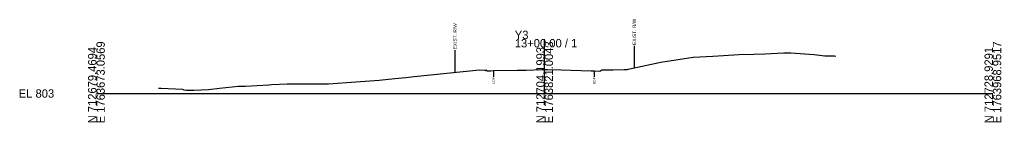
# Model space of a CAD drawing. Extents: x -26 to 2903, y -10 to 5022.
# Drawn here: x -25.7 to 302.8, y 2990.3 to 3024.8 of the extents above; entities that cross this region are included whole.
import ezdxf

# ---------------------------------------------------------------- set-up
doc = ezdxf.new("R2010")
doc.units = 0
for name, color, linetype in [('Default', 7, 'Continuous'), ('Exist Cross Section Cell', 7, 'Continuous'), ('Exist XS Ground Line', 7, 'Continuous'), ('Old_Level_10', 7, 'Continuous')]:
    doc.layers.add(name, color=color, linetype=linetype)

msp = doc.modelspace()

# ---------------------------------------------------------------- linework, layer by layer
at = {"layer": 'Exist Cross Section Cell'}
for p, q in [((150, 3000), (150, 3018.27)), ((0, 3000), (150, 3000)), ((150, 3000), (300, 3000))]:
    msp.add_line(p, q, dxfattribs=at)
at = {"layer": 'Exist XS Ground Line'}
msp.add_lwpolyline([(20.83, 3001.83), (21.66, 3001.81), (28.78, 3001.48), (29.25, 3001.28), (30.14, 3001.15), (32.55, 3001.09), (37.46, 3001.31), (41.24, 3001.83), (47.59, 3002.5), (49.93, 3002.41), (57.73, 3002.95), (58.61, 3002.97), (63.87, 3003.21), (67.3, 3003.22), (67.87, 3003.22), (68.71, 3003.25), (77.64, 3003.29), (83.66, 3003.69), (94.58, 3004.44), (99.87, 3005.07), (103.6, 3005.37), (106.37, 3005.72), (128.17, 3007.9), (129.89, 3007.87), (130.08, 3007.68), (130.2, 3007.67), (130.34, 3007.93), (130.88, 3007.56), (132, 3007.64), (132.83, 3007.69), (140.85, 3007.81), (143.79, 3007.85), (149.05, 3008), (150, 3008.03), (150.04, 3008.03), (150.91, 3008.02), (155.55, 3007.95), (165.56, 3007.66), (166.56, 3007.63), (166.72, 3007.63), (168.45, 3007.5), (168.51, 3007.54), (169.11, 3007.95), (171.73, 3007.94), (171.92, 3007.94), (172.86, 3007.97), (176.65, 3008.07), (177.59, 3008.1), (177.78, 3008.1), (177.91, 3008.14), (188.91, 3010.48), (189.54, 3010.63), (197.6, 3011.82), (199.68, 3012.15), (206.29, 3012.51), (209.81, 3012.79), (214.97, 3013.14), (219.95, 3013.17), (223.66, 3013.31), (230.09, 3013.63), (232.35, 3013.63), (240.23, 3013.14), (243.78, 3012.64), (246.96, 3012.67), (247.43, 3012.54)], dxfattribs=at)
at = {"layer": 'Old_Level_10'}
for p, q in [((180, 3015.98), (180, 3008.58)), ((120, 3014.49), (120, 3007.08)), ((132.83, 3007.69), (132.83, 3005.64)), ((166.56, 3007.63), (166.56, 3005.58))]:
    msp.add_line(p, q, dxfattribs=at)

# ---------------------------------------------------------------- texts
at = {"layer": 'Default'}
msp.add_text('-', height=0.0001, dxfattribs=at).set_placement((0, 3000))
at = {"layer": 'Exist Cross Section Cell'}
for s, p in [('Y3', (140, 3018.27)), ('13+00.00 / 1', (140, 3015.47)), ('EL 803', (-26, 2998.6))]:
    msp.add_text(s, height=2.8, dxfattribs=at).set_placement(p)
for s, p in [('E 1763673.0569', (2.8, 2990)), ('E 1763821.0043', (152.8, 2990)), ('E 1763968.9517', (302.8, 2990)), ('N 712679.4694', (0, 2990)), ('N 712704.1993', (150, 2990)), ('N 712728.9291', (300, 2990))]:
    msp.add_text(s, height=2.8, rotation=90, dxfattribs=at).set_placement(p)
at = {"layer": 'Old_Level_10'}
for s, height, p in [('EXIST. R/W', 1.181, (120.59, 3014.79)), ('EXIST. R/W', 1.181, (180.59, 3016.29)), ('EOP', 0.787, (133.23, 3003.24)), ('EOP', 0.787, (166.96, 3003.19))]:
    msp.add_text(s, height=height, rotation=90, dxfattribs=at).set_placement(p)

doc.saveas('drawing.dxf')
